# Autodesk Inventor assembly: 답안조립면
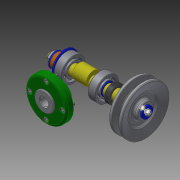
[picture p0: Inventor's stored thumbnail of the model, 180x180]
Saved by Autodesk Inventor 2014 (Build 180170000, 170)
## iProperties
Created: 2016-08
Part Number: 답안조립면
Document SubType Name: Assembly
Designer: user
Author: user
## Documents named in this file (20)
- C:\Users\user\Desktop\460808V1015\답안조립품.iam
- C:\Users\user\Desktop\460808V1015\본체.ipt
- C:\Users\user\Desktop\460808V1015\사이드 커버.ipt
- 사이드 커버.ipt
- C:\Users\user\Desktop\460808V1015\베어링 15 x 35 x 11.ipt
- C:\Users\user\Desktop\460808V1015\오일 실 15 25 7.ipt
- C:\Users\user\Desktop\460808V1015\편심축.ipt
- C:\Users\user\Desktop\460808V1015\탑 커버.ipt
- 탑 커버.ipt
- C:\Users\user\Desktop\460808V1015\탑 부시.ipt
- C:\Users\user\Desktop\460808V1015\V-벨트풀리.ipt
- C:\Users\user\Desktop\460808V1015\키 4 x 4 x 18.ipt
- C:\Users\user\Desktop\460808V1015\와셔 4x16.ipt
- C:\Users\user\Desktop\460808V1015\볼트 M4 x 10.ipt
- C:\Users\user\Desktop\460808V1015\멈춤링 35x1.6.ipt
- C:\Users\user\Desktop\460808V1015\멈춤링 15 x 1.ipt
- C:\Users\user\Desktop\460808V1015\부시2.ipt
- C:\Users\user\Desktop\460808V1015\와셔 10x21.ipt
- C:\Users\user\Desktop\460808V1015\너트 M10.ipt
- C:\Users\user\Desktop\460808V1015\볼트 M4 x 12.ipt
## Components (6 placed, 3 different names)
1. V-벨트풀리:1 — Angle:2, Insert:8, Insert:9
2. ISO 4017 M4 x 10:1 — Rigid:1
3. ISO 4762 M4 x 12:1 — Rigid:3
4. ISO 4762 M4 x 12:2 — Rigid:4
5. ISO 4762 M4 x 12:3 — Rigid:6
6. ISO 4762 M4 x 12:4 — Rigid:5
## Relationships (8: WeldJoint 5, Insert 2, Angle 1)
- Angle:2: V-벨트풀리:1
- Insert:8: V-벨트풀리:1
- Insert:9: V-벨트풀리:1
- Rigid:1 [WeldJoint]: ISO 4017 M4 x 10:1
- Rigid:3 [WeldJoint]: ISO 4762 M4 x 12:1
- Rigid:4 [WeldJoint]: ISO 4762 M4 x 12:2
- Rigid:5 [WeldJoint]: ISO 4762 M4 x 12:4
- Rigid:6 [WeldJoint]: ISO 4762 M4 x 12:3
